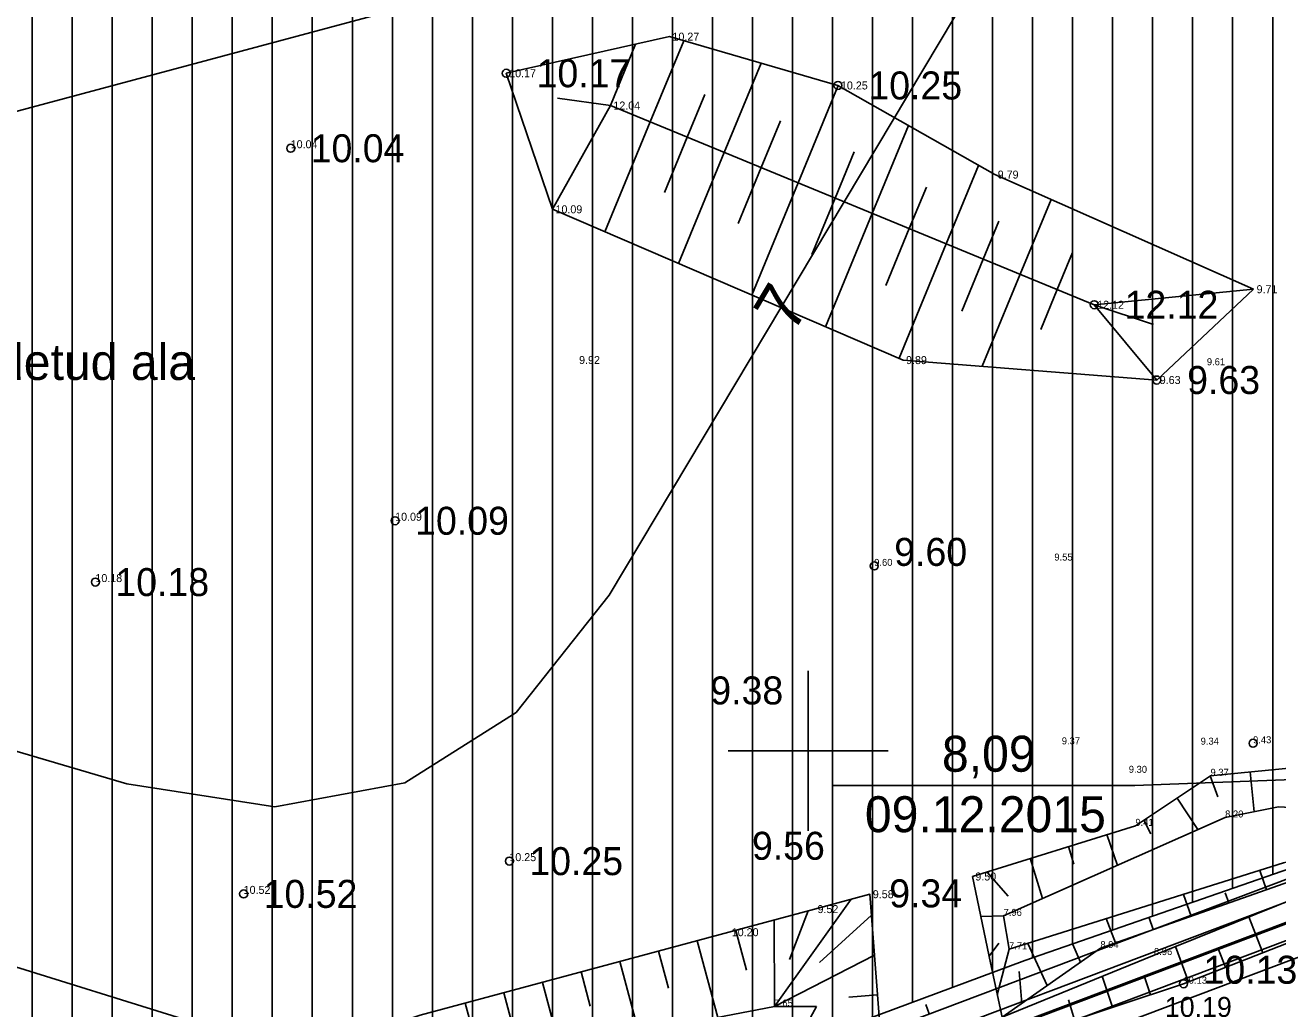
# Model space of a CAD drawing. Extents: x 433497 to 434382, y 6534486 to 6534993.
# Drawn here: x 434060.9 to 434123.5, y 6534787.1 to 6534836.3 of the extents above; entities that cross this region are included whole.
import ezdxf

# ---------------------------------------------------------------- set-up
doc = ezdxf.new("R2010")
doc.units = 0
for name, color, linetype in [('Default', 7, 'Continuous'), ('kataster', 7, 'Continuous'), ('KORGUS', 7, 'Continuous'), ('KORGUS-EH2000', 7, 'Continuous'), ('l__x00e4__bil__x00f5__iked', 7, 'Continuous'), ('Lamami horisontaal', 7, 'Continuous'), ('MAAMUDEL-EH2000', 7, 'Continuous'), ('MOOTKORG-EH2000', 7, 'Continuous'), ('PIIR', 7, 'Continuous'), ('RELJEEF', 7, 'Continuous'), ('Täide', 7, 'Continuous'), ('VEEKOGU', 7, 'Continuous'), ('VORK', 7, 'Continuous')]:
    doc.layers.add(name, color=color, linetype=linetype)

msp = doc.modelspace()

# ---------------------------------------------------------------- linework, layer by layer
at = {"layer": 'Default'}
msp.add_lwpolyline([(433617.12, 6534791.025), (433632.75, 6534606.045), (434137.38, 6534796.515), (434127.69, 6534855.6), (433968.21, 6534911.925), (433942.38, 6534904.035), (433920.99, 6534907.275)], close=True, dxfattribs=at)
msp.add_lwpolyline([(433617.12, 6534791.025), (433632.75, 6534606.045), (434137.38, 6534796.515), (434127.69, 6534855.6), (433968.21, 6534911.925), (433942.38, 6534904.035), (433920.99, 6534907.275)], close=True, dxfattribs=at)
msp.add_lwpolyline([(433617.12, 6534791.025), (433632.75, 6534606.045), (434137.38, 6534796.515), (434127.69, 6534855.6), (433968.21, 6534911.925), (433942.38, 6534904.035), (433920.99, 6534907.275)], close=True, dxfattribs=at)
at = {"layer": 'kataster'}
msp.add_lwpolyline([(433617.102, 6534791.002), (433632.769, 6534606.029), (434137.446, 6534796.469), (434127.827, 6534855.589), (433950.026, 6534918.39)], close=True, dxfattribs=at)
at = {"layer": 'KORGUS'}
for centre in [(434084.903, 6534833.879), (434101.486, 6534833.269), (434074.132, 6534830.129), (434114.292, 6534822.302), (434117.42, 6534818.54), (434079.353, 6534811.502), (434064.371, 6534808.435), (434085.061, 6534794.481), (434071.781, 6534792.843)]:
    msp.add_circle(centre, 0.2, dxfattribs=at)
at = {"layer": 'KORGUS-EH2000'}
for centre in [(434103.297, 6534809.244), (434122.233, 6534800.375), (434118.757, 6534788.35)]:
    msp.add_circle(centre, 0.2, dxfattribs=at)
at = {"layer": 'l__x00e4__bil__x00f5__iked'}
for points in [[(433837.129, 6534901.88), (433863.279, 6534885.992), (433986.579, 6534812.177), (434090.185, 6534779.904), (434120.969, 6534768.153)], [(433620.07, 6534691.039), (433627.105, 6534692.187), (433736.834, 6534712.709), (433742.792, 6534710.723), (433822.234, 6534766.498), (433986.579, 6534812.177), (434120.472, 6534848.091), (434132.163, 6534850.175)]]:
    msp.add_lwpolyline(points, dxfattribs=at)
at = {"layer": 'Lamami horisontaal'}
msp.add_lwpolyline([(433993.085, 6534819.831), (434065.946, 6534798.347), (434073.345, 6534797.199), (434079.829, 6534798.389), (434085.398, 6534801.916), (434090.054, 6534807.779), (434115.176, 6534849.864), (434115.208, 6534849.92), (434115.238, 6534849.976), (434115.267, 6534850.033), (434115.294, 6534850.091), (434115.398, 6534850.325), (434115.425, 6534850.383), (434115.455, 6534850.439), (434115.487, 6534850.494), (434115.522, 6534850.548), (434120.641, 6534858.055)], dxfattribs=at)
at = {"layer": 'PIIR'}
for points in [[(433632.021, 6534604.835), (434138.248, 6534795.936), (434128.468, 6534856.135), (433968.226, 6534912.818), (433942.33, 6534904.85), (433920.952, 6534908.165), (433616.327, 6534791.524), (433632.021, 6534604.835)], [(433632.732, 6534605.959), (434137.353, 6534796.454), (434127.754, 6534855.539), (433968.208, 6534911.976), (433942.39, 6534904.031), (433921.04, 6534907.341), (433617.174, 6534790.992), (433632.732, 6534605.959)], [(433633.446, 6534604.304), (434134.891, 6534793.6)]]:
    msp.add_lwpolyline(points, dxfattribs=at)
for points in [[(433618.234, 6534790.327), (433921.149, 6534906.313), (433942.464, 6534903.008), (433968.187, 6534910.923), (434126.862, 6534854.794), (434136.235, 6534797.101), (433633.617, 6534607.362)], [(433619.24, 6534789.695), (433634.52, 6534608.851), (434135.141, 6534797.808), (434125.908, 6534854.108), (433968.165, 6534909.82), (433942.53, 6534901.99), (433921.212, 6534905.219)], [(433619.24, 6534789.695), (433634.52, 6534608.851), (434135.141, 6534797.808), (434125.908, 6534854.108), (433968.165, 6534909.82), (433942.53, 6534901.99), (433921.212, 6534905.219)]]:
    msp.add_lwpolyline(points, close=True, dxfattribs=at)
at = {"layer": 'RELJEEF'}
for p, q in [((434092.102, 6534831.445), (434093.774, 6534835.503)), ((434090.112, 6534832.265), (434091.374, 6534835.33)), ((434095.8, 6534829.922), (434097.639, 6534834.383)), ((434099.499, 6534828.398), (434101.502, 6534833.26)), ((434090.112, 6534832.265), (434087.218, 6534827.076)), ((434090.112, 6534832.265), (434087.464, 6534832.638)), ((434114.292, 6534822.302), (434090.112, 6534832.265)), ((434094.829, 6534832.813), (434093.951, 6534830.683)), ((434092.102, 6534831.445), (434089.837, 6534825.949)), ((434098.61, 6534831.492), (434097.649, 6534829.16)), ((434103.197, 6534826.874), (434105.007, 6534831.266)), ((434092.813, 6534827.921), (434093.951, 6534830.683)), ((434095.8, 6534829.922), (434093.512, 6534824.368)), ((434102.301, 6534829.949), (434101.348, 6534827.636)), ((434096.499, 6534826.368), (434097.649, 6534829.16)), ((434106.895, 6534825.35), (434108.511, 6534829.272)), ((434099.499, 6534828.398), (434097.187, 6534822.786)), ((434105.903, 6534828.19), (434105.046, 6534826.112)), ((434100.186, 6534824.816), (434101.348, 6534827.636)), ((434110.594, 6534823.826), (434112.134, 6534827.565)), ((434103.197, 6534826.874), (434100.861, 6534821.205)), ((434103.872, 6534823.263), (434105.046, 6534826.112)), ((434109.525, 6534826.482), (434108.744, 6534824.588)), ((434106.895, 6534825.35), (434104.536, 6534819.624)), ((434113.203, 6534824.91), (434112.443, 6534823.064)), ((434107.673, 6534821.989), (434108.744, 6534824.588)), ((434110.594, 6534823.826), (434108.698, 6534819.225)), ((434111.618, 6534821.062), (434112.443, 6534823.064)), ((434114.292, 6534822.302), (434122.26, 6534823.08)), ((434114.292, 6534822.302), (434117.42, 6534818.54)), ((434114.292, 6534822.302), (434117.259, 6534821.322)), ((434120.467, 6534797.703), (434120.096, 6534798.741)), ((434122.084, 6534798.939), (434122.28, 6534796.947)), ((434118.431, 6534797.632), (434119.479, 6534796.06)), ((434117.119, 6534795.845), (434116.767, 6534796.523)), ((434114.917, 6534795.806), (434115.449, 6534794.269)), ((434113.279, 6534794.324), (434113.004, 6534795.22)), ((434111.092, 6534794.634), (434111.713, 6534792.609)), ((434122.907, 6534793.052), (434122.566, 6534794.02)), ((434109.997, 6534792.728), (434108.934, 6534793.939)), ((434119.133, 6534791.726), (434118.749, 6534792.818)), ((434120.839, 6534792.904), (434121.02, 6534792.389)), ((434098.317, 6534787.207), (434102.138, 6534792.573)), ((434098.304, 6534791.54), (434098.317, 6534787.207)), ((434099.058, 6534789.557), (434099.993, 6534791.995)), ((434100.564, 6534789.416), (434103.16, 6534791.775)), ((434109.765, 6534791.743), (434108.625, 6534791.708)), ((434115.359, 6534790.4), (434114.897, 6534791.604)), ((434117.043, 6534791.639), (434117.246, 6534791.063)), ((434122.723, 6534789.902), (434122.022, 6534791.694)), ((434096.909, 6534789.03), (434096.373, 6534791.019)), ((434094.442, 6534790.499), (434095.475, 6534786.664)), ((434109.518, 6534790.371), (434109.038, 6534789.736)), ((434111.942, 6534788.26), (434110.981, 6534790.37)), ((434113.218, 6534790.306), (434113.603, 6534789.43)), ((434093.008, 6534788.133), (434092.511, 6534789.978)), ((434103.313, 6534789.781), (434098.317, 6534787.207)), ((434110.035, 6534790.072), (434109.45, 6534787.793)), ((434118.998, 6534788.444), (434118.351, 6534790.214)), ((434120.513, 6534790.06), (434120.86, 6534789.173)), ((434090.58, 6534789.458), (434091.536, 6534785.911)), ((434086.717, 6534788.417), (434087.785, 6534784.457)), ((434089.107, 6534787.236), (434088.649, 6534788.937)), ((434110.55, 6534788.957), (434110.675, 6534787.369)), ((434115.207, 6534787.171), (434114.691, 6534788.722)), ((434116.806, 6534788.689), (434117.105, 6534787.801)), ((434085.375, 6534785.713), (434084.786, 6534787.896)), ((434102.028, 6534787.676), (434103.466, 6534787.787)), ((434082.855, 6534787.376), (434084.057, 6534782.917)), ((434105.873, 6534787.316), (434106.037, 6534786.852)), ((434113.009, 6534787.553), (434113.309, 6534786.54))]:
    msp.add_line(p, q, dxfattribs=at)
for points in [[(434002.621, 6534891.199), (434008.357, 6534898.477), (434008.844, 6534898.428), (434009.684, 6534897.899), (434020.673, 6534893.319), (434025.184, 6534891.367), (434026.4, 6534888.82), (434028.53, 6534881.31), (434029.71, 6534869.667), (434036.879, 6534848.772), (434040.385, 6534828.949), (434036.914, 6534815.456), (434039.48, 6534802.82), (434040.271, 6534794.377), (434046.22, 6534786.31), (434052.87, 6534782.4), (434066.43, 6534782.05), (434080.61, 6534786.771), (434096.029, 6534790.927), (434100.314, 6534792.082), (434103.079, 6534792.827), (434103.7, 6534784.75)], [(434093.065, 6534835.709), (434084.903, 6534833.879), (434087.218, 6534827.076), (434104.741, 6534819.536), (434117.42, 6534818.54), (434122.26, 6534823.08)], [(434122.26, 6534823.08), (434109.321, 6534828.812), (434101.486, 6534833.269), (434093.065, 6534835.709)], [(434108.205, 6534793.713), (434116.351, 6534796.246), (434120.106, 6534798.748), (434129.148, 6534799.622), (434131.664, 6534803.782), (434132.866, 6534809.14), (434135.095, 6534810.674), (434136.304, 6534808.284), (434137.928, 6534815.607), (434143.009, 6534816.202), (434143.311, 6534815.613)], [(434109.687, 6534786.673), (434112.222, 6534786.179), (434118.757, 6534788.35), (434129.51, 6534792.559), (434134.019, 6534795.71), (434135.253, 6534797.374), (434140.289, 6534808.003), (434143.311, 6534815.613)], [(434109.687, 6534786.673), (434117.282, 6534789.783), (434131.587, 6534795.543), (434133.62, 6534797.699), (434138.093, 6534806.728), (434141.209, 6534813.9)], [(434141.209, 6534813.9), (434137.097, 6534806.833), (434136.556, 6534805.855), (434135.205, 6534807.159), (434134.085, 6534808.648), (434132.177, 6534799.345), (434128.834, 6534796.902), (434123.508, 6534797.188), (434120.837, 6534796.664), (434109.765, 6534791.743), (434109.765, 6534791.743), (434110.035, 6534790.072)], [(434110.035, 6534790.072), (434110.035, 6534790.072), (434110.035, 6534790.072), (434123.746, 6534794.392), (434129.931, 6534795.881), (434132.492, 6534798.11), (434133.601, 6534803.349), (434135.205, 6534807.159)], [(434133.62, 6534797.699), (434131.587, 6534795.543), (434125.259, 6534793.878), (434114.603, 6534790.134), (434109.687, 6534786.673), (434109.111, 6534789.39), (434108.205, 6534793.713)]]:
    msp.add_lwpolyline(points, dxfattribs=at)
at = {"layer": 'Täide'}
for p, q in [((434061.213, 6534770.471), (434061.213, 6534875.946)), ((434063.213, 6534771.29), (434063.213, 6534875.289)), ((434065.213, 6534771.962), (434065.213, 6534874.534)), ((434067.213, 6534772.635), (434067.213, 6534873.778)), ((434069.213, 6534773.307), (434069.213, 6534873.023)), ((434071.213, 6534773.979), (434071.213, 6534872.268)), ((434073.213, 6534774.651), (434073.213, 6534871.512)), ((434075.213, 6534775.323), (434075.213, 6534870.757)), ((434077.213, 6534776.152), (434077.213, 6534870.002)), ((434079.213, 6534777.334), (434079.213, 6534869.246)), ((434081.213, 6534778.516), (434081.213, 6534868.491)), ((434083.213, 6534779.673), (434083.213, 6534867.736)), ((434085.213, 6534780.367), (434085.213, 6534866.98)), ((434087.213, 6534781.061), (434087.213, 6534866.225)), ((434089.213, 6534781.755), (434089.213, 6534865.469)), ((434091.213, 6534782.449), (434091.213, 6534864.714)), ((434093.213, 6534783.144), (434093.213, 6534863.959)), ((434095.213, 6534783.838), (434095.213, 6534863.203)), ((434097.213, 6534784.532), (434097.213, 6534862.448)), ((434099.213, 6534785.226), (434099.213, 6534861.785)), ((434101.213, 6534785.934), (434101.213, 6534861.198)), ((434103.213, 6534786.679), (434103.213, 6534860.611)), ((434105.213, 6534787.424), (434105.213, 6534860.024)), ((434107.213, 6534788.169), (434107.213, 6534859.437)), ((434109.213, 6534788.914), (434109.213, 6534858.85)), ((434111.213, 6534789.649), (434111.213, 6534858.263)), ((434113.213, 6534790.344), (434113.213, 6534857.676)), ((434115.213, 6534791.039), (434115.213, 6534857.089)), ((434117.213, 6534791.735), (434117.213, 6534856.502)), ((434119.213, 6534792.43), (434119.213, 6534855.915)), ((434121.213, 6534793.125), (434121.213, 6534855.328)), ((434123.213, 6534793.82), (434123.213, 6534854.741))]:
    msp.add_line(p, q, dxfattribs=at)
msp.add_lwpolyline([(434053.953, 6534766.741), (434062.043, 6534770.897), (434076.601, 6534775.79), (434083.107, 6534779.636), (434100.67, 6534785.732), (434110.817, 6534789.511), (434130.115, 6534796.22), (434132.899, 6534799.258), (434133.017, 6534809.88), (434125.182, 6534852.548), (434123.278, 6534854.722), (434098.113, 6534862.108), (434062.901, 6534875.407), (434022.093, 6534888.443), (434021.059, 6534887.256), (434037.893, 6534864.165), (434021.392, 6534791.18), (434023.3, 6534781.148), (434025.663, 6534773.898), (434039.607, 6534770.357), (434045.083, 6534767.989), (434045.714, 6534765.502), (434044.882, 6534761.539)], dxfattribs=at)
at = {"layer": 'VEEKOGU'}
for points in [[(434100.405, 6534787.207), (434098.317, 6534787.207), (434089.545, 6534785.531), (434086.602, 6534783.735), (434074.461, 6534779.832), (434066.338, 6534777.192), (434050.88, 6534777.91), (434044.67, 6534782.72), (434037.09, 6534794.99), (434032.35, 6534809.44), (434034.87, 6534823.21), (434035.905, 6534837.207), (434031.53, 6534853.98), (434027.762, 6534864.072)], [(434101.202, 6534798.262), (434116.33, 6534798.262), (434133.022, 6534798.9)], [(434050.128, 6534758.038), (434051.667, 6534760.055), (434049.568, 6534761.922), (434050.115, 6534764.979), (434053.54, 6534767.639), (434061.885, 6534771.617), (434075.613, 6534776.761), (434082.778, 6534780.666), (434100.118, 6534786.667), (434100.405, 6534787.207)]]:
    msp.add_lwpolyline(points, dxfattribs=at)
msp.add_lwpolyline([(434110.035, 6534790.072), (434109.765, 6534791.743), (434120.837, 6534796.664), (434123.508, 6534797.188), (434128.834, 6534796.902), (434132.177, 6534799.345), (434132.972, 6534799.1), (434132.492, 6534798.11), (434129.931, 6534795.881), (434123.746, 6534794.392)], close=True, dxfattribs=at)
at = {"layer": 'VORK'}
for p, q in [((434100, 6534804), (434100, 6534796)), ((434096, 6534800), (434104, 6534800))]:
    msp.add_line(p, q, dxfattribs=at)

# ---------------------------------------------------------------- texts
at = {"layer": 'KORGUS-EH2000'}
for s, p in [(' 10.17', (434085.903, 6534833.179)), (' 10.25', (434102.486, 6534832.569)), ('10.04', (434075.132, 6534829.429)), (' 12.12', (434115.292, 6534821.602)), (' 9.63', (434118.42, 6534817.84)), ('10.09', (434080.353, 6534810.802)), ('9.60', (434104.297, 6534809.244)), ('10.18', (434065.371, 6534807.735)), ('9.38', (434095.106, 6534802.317)), ('9.56', (434097.187, 6534794.549)), ('10.25', (434086.061, 6534793.781)), ('10.52', (434072.781, 6534792.143)), ('9.34', (434104.05, 6534792.169)), ('10.13', (434119.757, 6534788.35))]:
    msp.add_text(s, height=1.4, dxfattribs=at).set_placement(p)
at = {"layer": 'Lamami horisontaal'}
msp.add_text('7', height=2.4, rotation=59.16483, dxfattribs=at).set_placement((434099.225, 6534820.802))
at = {"layer": 'MAAMUDEL-EH2000'}
for s, p in [(' 10.27', (434093.065, 6534835.509)), (' 10.27', (434093.065, 6534835.509)), (' 10.17', (434084.903, 6534833.679)), (' 10.25', (434101.486, 6534833.069)), (' 12.04', (434090.112, 6534832.065)), ('10.04', (434074.132, 6534830.129)), (' 9.79', (434109.321, 6534828.612)), (' 10.09', (434087.218, 6534826.876)), (' 9.71', (434122.26, 6534822.88)), (' 12.12', (434114.292, 6534822.102)), ('9.92', (434088.547, 6534819.339)), (' 9.89', (434104.741, 6534819.336)), (' 9.63', (434117.42, 6534818.34)), ('10.09', (434079.353, 6534811.502)), ('10.18', (434064.371, 6534808.435)), ('10.25', (434085.061, 6534794.481)), (' 9.50', (434108.205, 6534793.513)), ('10.52', (434071.781, 6534792.843)), (' 9.58', (434103.079, 6534792.627)), (' 9.52', (434100.314, 6534791.882)), (' 10.20', (434096.029, 6534790.727))]:
    msp.add_text(s, height=0.4, dxfattribs=at).set_placement(p)
at = {"layer": 'MOOTKORG-EH2000'}
for s, height, p in [('9.61', 0.35, (434119.924, 6534819.278)), ('9.55', 0.35, (434112.301, 6534809.511)), ('9.60', 0.35, (434103.297, 6534809.244)), ('9.37', 0.35, (434112.672, 6534800.321)), ('9.34', 0.35, (434119.613, 6534800.305)), ('9.43', 0.35, (434122.233, 6534800.375)), ('9.30', 0.35, (434116.021, 6534798.897)), ('9.37', 0.35, (434120.106, 6534798.748)), ('9.41', 0.35, (434116.351, 6534796.246)), ('8.20', 0.35, (434120.837, 6534796.664)), ('7.96', 0.35, (434109.765, 6534791.743)), ('7.71', 0.35, (434110.035, 6534790.072)), ('8.94', 0.35, (434114.603, 6534790.134)), ('8.96', 0.35, (434117.282, 6534789.783)), ('10.13', 0.35, (434118.757, 6534788.35)), ('7.65', 0.35, (434098.317, 6534787.207)), ('10.19', 1, (434117.824, 6534786.689))]:
    msp.add_text(s, height=height, dxfattribs=at).set_placement(p)
at = {"layer": 'RELJEEF'}
msp.add_text('täidetud ala', height=1.8, dxfattribs=at).set_placement((434056.908, 6534818.542))
at = {"layer": 'VEEKOGU'}
for s, p in [('8,09', (434106.681, 6534798.952)), ('09.12.2015', (434102.831, 6534795.927))]:
    msp.add_text(s, height=1.8, dxfattribs=at).set_placement(p)

doc.saveas('drawing.dxf')
